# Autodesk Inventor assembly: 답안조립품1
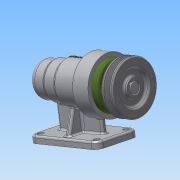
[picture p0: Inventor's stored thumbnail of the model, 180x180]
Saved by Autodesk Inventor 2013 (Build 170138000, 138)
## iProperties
Created: 2016-06
Part Number: 답안조립품1
Document SubType Name: Assembly
Designer: Administrator
Author: Administrator
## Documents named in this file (12)
- C:\Users\Administrator\Desktop\460608V1003\답안조립품1.iam
- C:\Users\Administrator\Desktop\460608V1003\본체.ipt
- C:\Users\Administrator\Desktop\460608V1003\축.ipt
- C:\Users\Administrator\Desktop\460608V1003\키 5 x 5 x 16.ipt
- C:\Users\Administrator\Desktop\460608V1003\V벨트풀리.ipt
- C:\Users\Administrator\Desktop\460608V1003\멈춤나사 M3x8.ipt
- C:\Users\Administrator\Desktop\460608V1003\커버.ipt
- C:\Users\Administrator\Desktop\460608V1003\오일 실.ipt
- C:\Users\Administrator\Desktop\460608V1003\베어링 6004.ipt
- C:\Users\Administrator\Desktop\460608V1003\베어링 51202.ipt
- C:\Users\Administrator\Desktop\460608V1003\어댑터슬리브.ipt
- C:\Users\Administrator\Desktop\460608V1003\볼트 M4 x 12.ipt
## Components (6 placed, 2 different names)
1. V벨트풀리:1
2. ISO 4762 M4 x 12:1
3. ISO 4762 M4 x 12:2
4. ISO 4762 M4 x 12:3
5. ISO 4762 M4 x 12:4
6. ISO 4762 M4 x 12:5
